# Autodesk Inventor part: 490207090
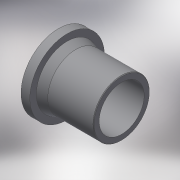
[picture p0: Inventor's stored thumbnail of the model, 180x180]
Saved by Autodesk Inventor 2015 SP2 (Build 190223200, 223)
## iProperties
Created: 2017-07
Part Number: 490207090
Material: Generic
Description: Stub Flange 90
Document SubType Name: Modeling
Designer: Кирилл
Mass: 495.511 g
Surface Area: 955.843 cm^2
Volume: 495.511 cm^3
Density: 1 g/cm^3
Appearance: Default
Author: Кирилл
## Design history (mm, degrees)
derived "490207.ipt"
feature "Solid1::490207.ipt"
tag "TaggingFeature1"
body "Solid1"
other parameters: "d1" = 105, "d3" = 72, "d4" = 138, "d5" = 17, "d6" = 96, "d17" = 1.8, "d18" = 1.8, "d19" = 1.8, "d21" = 1.8, "d24" = 1.8, "d25" = 1.8, "d26" = 0.9, "d27" = 0, "d32" = 0.9, "L_1" = 96, "D_" = 138, "D_1" = 105, "a_" = 17
